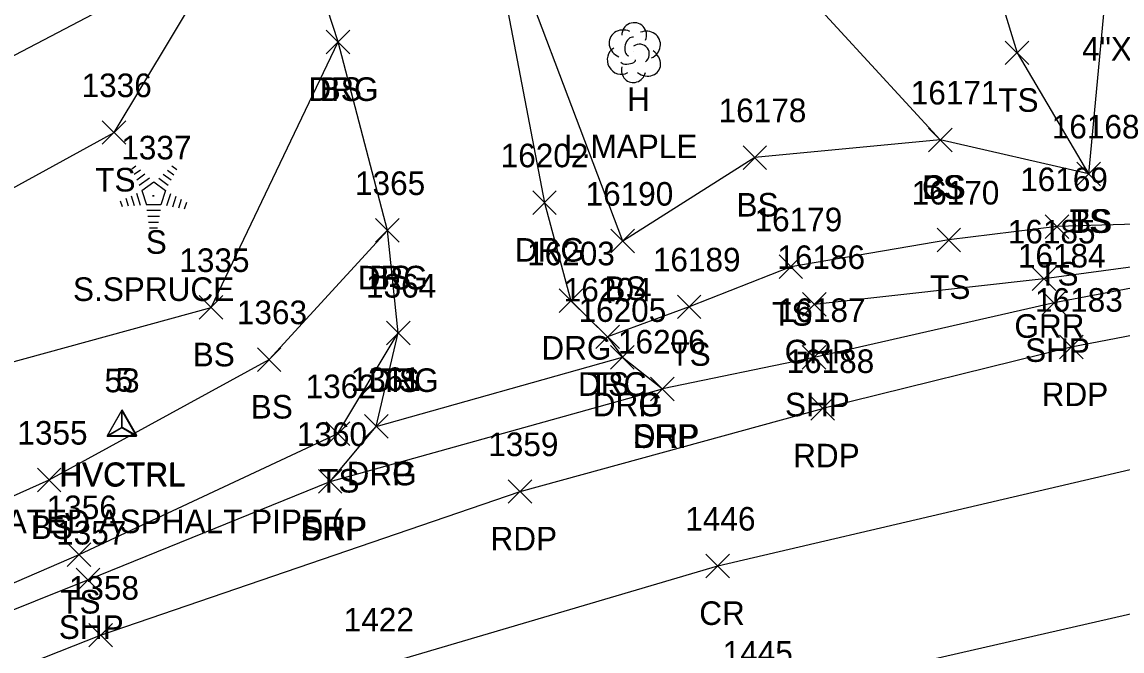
# Model space of a CAD drawing. Extents: x 1606530 to 1613020, y 784959 to 789666.
# Drawn here: x 1609059.8 to 1609153.1, y 788414.2 to 788467.6 of the extents above; entities that cross this region are included whole.
import ezdxf

# ---------------------------------------------------------------- set-up
doc = ezdxf.new("R2010")
doc.units = 0
for name, color, linetype in [('C_A', 7, 'Continuous'), ('C_C', 7, 'Continuous'), ('C_I', 7, 'Continuous'), ('CPSM', 7, 'Continuous'), ('L_A', 7, 'Continuous'), ('L_C', 7, 'Continuous'), ('L_I', 7, 'Continuous'), ('L_TIC', 7, 'Continuous'), ('LAPB', 7, 'Continuous'), ('LELB', 7, 'Continuous'), ('LTC', 7, 'Continuous'), ('LTD', 7, 'Continuous'), ('M_C', 7, 'Continuous'), ('P_A', 7, 'Continuous'), ('P_I', 7, 'Continuous'), ('P_TIC', 7, 'Continuous'), ('PET', 7, 'Continuous'), ('PRC', 7, 'Continuous'), ('PSP', 7, 'Continuous'), ('R_A', 7, 'Continuous'), ('R_I', 7, 'Continuous'), ('R_TIC', 7, 'Continuous'), ('RDG', 7, 'Continuous'), ('RDP', 7, 'Continuous'), ('RGR', 7, 'Continuous')]:
    doc.layers.add(name, color=color, linetype=linetype)

msp = doc.modelspace()

# ---------------------------------------------------------------- linework, layer by layer
at = {"layer": 'CPSM'}
for p, q in [((1609067.029, 788432.449), (1609068.279, 788434.614)), ((1609067.07, 788432.503), (1609068.32, 788434.668)), ((1609069.529, 788432.449), (1609068.279, 788434.614)), ((1609068.279, 788433.17), (1609068.279, 788434.614)), ((1609069.57, 788432.503), (1609068.32, 788434.668)), ((1609068.32, 788433.224), (1609068.32, 788434.668)), ((1609067.029, 788432.449), (1609068.279, 788433.17)), ((1609067.07, 788432.503), (1609068.32, 788433.224)), ((1609068.279, 788433.17), (1609068.279, 788433.17)), ((1609068.279, 788433.17), (1609069.529, 788432.449)), ((1609068.32, 788433.224), (1609068.32, 788433.224)), ((1609068.32, 788433.224), (1609069.57, 788432.503)), ((1609067.029, 788432.449), (1609069.529, 788432.449)), ((1609067.07, 788432.503), (1609069.57, 788432.503))]:
    msp.add_line(p, q, dxfattribs=at)
at = {"layer": 'L_TIC'}
for points in [[(1609085.615, 788464.867), (1609087.615, 788466.867)], [(1609087.615, 788464.867), (1609085.615, 788466.867)], [(1609143.18, 788463.944), (1609145.18, 788465.944)], [(1609145.18, 788463.944), (1609143.18, 788465.944)], [(1609066.622, 788457.189), (1609068.622, 788459.189)], [(1609068.622, 788457.189), (1609066.622, 788459.189)], [(1609136.675, 788456.565), (1609138.675, 788458.565)], [(1609138.675, 788456.565), (1609136.675, 788458.565)], [(1609136.675, 788456.565), (1609138.675, 788458.565)], [(1609138.675, 788456.565), (1609136.675, 788458.565)], [(1609120.952, 788455.066), (1609122.952, 788457.066)], [(1609122.952, 788455.066), (1609120.952, 788457.066)], [(1609149.242, 788453.683), (1609151.242, 788455.683)], [(1609151.242, 788453.683), (1609149.242, 788455.683)], [(1609149.242, 788453.683), (1609151.242, 788455.683)], [(1609151.242, 788453.683), (1609149.242, 788455.683)], [(1609089.795, 788448.892), (1609091.795, 788450.892)], [(1609091.795, 788448.892), (1609089.795, 788450.892)], [(1609146.57, 788449.219), (1609148.57, 788451.219)], [(1609148.57, 788449.219), (1609146.57, 788451.219)], [(1609109.755, 788447.99), (1609111.755, 788449.99)], [(1609111.755, 788447.99), (1609109.755, 788449.99)], [(1609137.4, 788448.085), (1609139.4, 788450.085)], [(1609139.4, 788448.085), (1609137.4, 788450.085)], [(1609124.003, 788445.816), (1609126.003, 788447.816)], [(1609126.003, 788445.816), (1609124.003, 788447.816)], [(1609074.854, 788442.367), (1609076.854, 788444.367)], [(1609076.854, 788442.367), (1609074.854, 788444.367)], [(1609115.381, 788442.414), (1609117.381, 788444.414)], [(1609117.381, 788442.414), (1609115.381, 788444.414)], [(1609090.726, 788440.196), (1609092.726, 788442.196)], [(1609092.726, 788440.196), (1609090.726, 788442.196)], [(1609108.467, 788439.866), (1609110.467, 788441.866)], [(1609110.467, 788439.866), (1609108.467, 788441.866)], [(1609079.774, 788437.941), (1609081.774, 788439.941)], [(1609081.774, 788437.941), (1609079.774, 788439.941)], [(1609085.607, 788431.669), (1609087.607, 788433.669)], [(1609087.607, 788431.669), (1609085.607, 788433.669)], [(1609061.123, 788427.733), (1609063.123, 788429.733)], [(1609063.123, 788427.733), (1609061.123, 788429.733)], [(1609063.659, 788421.412), (1609065.659, 788423.412)], [(1609065.659, 788421.412), (1609063.659, 788423.412)]]:
    msp.add_lwpolyline(points, dxfattribs=at)
at = {"layer": 'LAPB'}
msp.add_lwpolyline([(1609039.186, 788456.559), (1609048.843, 788460.874), (1609049.597, 788459.75), (1609077.276, 788474.239), (1609077.034, 788475.297)], dxfattribs=at)
at = {"layer": 'LELB'}
for points in [[(1609129.406, 788518.122), (1609137.084, 788488.072), (1609144.18, 788464.944), (1609150.242, 788454.683)], [(1609137.675, 788457.565), (1609120.211, 788476.589), (1609108.336, 788494.696), (1609102.619, 788504.963)], [(1609154.118, 788496.013), (1609150.242, 788454.683), (1609137.675, 788457.565), (1609121.952, 788456.066), (1609110.755, 788448.99), (1609098.581, 788481.172)], [(1609023.982, 788453.352), (1609032.544, 788443.85), (1609054.318, 788450.9), (1609067.622, 788458.189), (1609077.276, 788474.239)], [(1609032.544, 788443.85), (1609044.285, 788434.696), (1609075.854, 788443.367), (1609086.615, 788465.867)], [(1609168.452, 788450.858), (1609147.57, 788450.219), (1609138.4, 788449.085), (1609125.003, 788446.816), (1609116.381, 788443.414), (1609109.467, 788440.866)], [(1608946.183, 788421.743), (1608965.259, 788393.752), (1608969.902, 788390.672), (1608981.426, 788393.597), (1608995.3, 788400.266), (1609013.646, 788407.887), (1609037.315, 788417.629), (1609062.123, 788428.733), (1609080.774, 788438.941), (1609090.795, 788449.892)], [(1608977.618, 788385.058), (1608987.682, 788388.705), (1609017.024, 788403.26), (1609039.259, 788411.433), (1609064.659, 788422.412), (1609086.607, 788432.669), (1609091.726, 788441.196)]]:
    msp.add_lwpolyline(points, dxfattribs=at)
at = {"layer": 'LTC'}
for p, q in [((1609069.124, 788455.118), (1609069.478, 788455.376)), ((1609069.333, 788454.653), (1609069.863, 788455.037)), ((1609072.151, 788455.011), (1609072.7, 788454.611)), ((1609072.522, 788455.359), (1609072.941, 788455.054)), ((1609069.543, 788454.187), (1609070.247, 788454.698)), ((1609069.753, 788453.721), (1609070.631, 788454.359)), ((1609071.409, 788454.314), (1609072.218, 788453.725)), ((1609071.78, 788454.662), (1609072.459, 788454.168)), ((1609069.977, 788453.266), (1609070.989, 788454.001)), ((1609069.977, 788453.266), (1609070.364, 788452.073)), ((1609070.989, 788454.001), (1609071.986, 788453.276)), ((1609071.986, 788453.276), (1609071.595, 788452.073)), ((1609068.156, 788452.398), (1609068.308, 788451.93)), ((1609068.612, 788452.614), (1609068.823, 788451.963)), ((1609069.067, 788452.831), (1609069.338, 788451.996)), ((1609069.523, 788453.047), (1609069.853, 788452.028)), ((1609072.423, 788453.005), (1609072.085, 788451.966)), ((1609072.868, 788452.755), (1609072.58, 788451.87)), ((1609073.313, 788452.505), (1609073.075, 788451.775)), ((1609073.757, 788452.254), (1609073.57, 788451.68)), ((1609071.595, 788452.073), (1609070.364, 788452.073)), ((1609071.556, 788451.573), (1609070.412, 788451.573)), ((1609071.473, 788451.073), (1609070.484, 788451.073)), ((1609071.389, 788450.573), (1609070.557, 788450.573)), ((1609071.305, 788450.073), (1609070.63, 788450.073))]:
    msp.add_line(p, q, dxfattribs=at)
at = {"layer": 'LTD'}
msp.add_line((1609111.677, 788465.016), (1609111.677, 788465.016), dxfattribs=at)
msp.add_line((1609111.677, 788465.016), (1609111.677, 788465.016), dxfattribs=at)
msp.add_arc((1609111.723, 788466.45), 1.047, 335.52715, 180.95627, dxfattribs=at)
for centre, major_axis, ratio, start_param, end_param in [((1609110.885, 788465.683), (1.21, -0.512), 0.895232, 1.570796, 4.712389), ((1609111.468, 788465.475), (-0.208, -0.792), 0.645439, 3.141593, 6.283185), ((1609112.718, 788465.6), (-1.141, -0.483), 0.949671, 1.570796, 4.712389), ((1609110.594, 788464.308), (0.584, -1.042), 0.959034, 3.141593, 6.283185), ((1609112.177, 788464.85), (-0.5, 0.667), 0.989748, 3.141593, 6.283185), ((1609111.219, 788464.266), (-0.625, -0.083), 0.423636, 0, 3.141593), ((1609112.677, 788464.183), (-1.09, 0.792), 0.841452, 1.570796, 4.712389), ((1609111.677, 788463.516), (0.265, 1.061), 0.942809, 1.570796, 4.712389)]:
    msp.add_ellipse(centre, major_axis=major_axis, ratio=ratio, start_param=start_param, end_param=end_param, dxfattribs=at)
at = {"layer": 'P_TIC'}
for points in [[(1609146.32, 788442.745), (1609148.32, 788444.745)], [(1609148.32, 788442.745), (1609146.32, 788444.745)], [(1609147.778, 788438.997), (1609149.778, 788440.997)], [(1609149.778, 788438.997), (1609147.778, 788440.997)], [(1609125.968, 788438.128), (1609127.968, 788440.128)], [(1609127.968, 788438.128), (1609125.968, 788440.128)], [(1609113.118, 788435.455), (1609115.118, 788437.455)], [(1609115.118, 788435.455), (1609113.118, 788437.455)], [(1609113.118, 788435.455), (1609115.118, 788437.455)], [(1609115.118, 788435.455), (1609113.118, 788437.455)], [(1609126.707, 788433.803), (1609128.707, 788435.803)], [(1609128.707, 788433.803), (1609126.707, 788435.803)], [(1609126.707, 788433.803), (1609128.707, 788435.803)], [(1609128.707, 788433.803), (1609126.707, 788435.803)], [(1609084.948, 788427.615), (1609086.948, 788429.615)], [(1609086.948, 788427.615), (1609084.948, 788429.615)], [(1609101.049, 788426.759), (1609103.049, 788428.759)], [(1609103.049, 788426.759), (1609101.049, 788428.759)], [(1609117.805, 788420.444), (1609119.805, 788422.444)], [(1609119.805, 788420.444), (1609117.805, 788422.444)], [(1609064.41, 788419.262), (1609066.41, 788421.262)], [(1609066.41, 788419.262), (1609064.41, 788421.262)], [(1609065.482, 788414.581), (1609067.482, 788416.581)], [(1609067.482, 788414.581), (1609065.482, 788416.581)]]:
    msp.add_lwpolyline(points, dxfattribs=at)
at = {"layer": 'PET'}
for points in [[(1609713.165, 788438.627), (1609680.929, 788440.448), (1609651.997, 788442.015), (1609625.849, 788443.733), (1609580.961, 788446.419), (1609565.084, 788447.467), (1609525.711, 788449.455), (1609486.159, 788451.542), (1609451.915, 788453.585), (1609423.874, 788454.943), (1609378.56, 788456.924), (1609332.013, 788457.666), (1609286.402, 788456.921), (1609233.035, 788453.523), (1609189.077, 788447.384), (1609175.759, 788445.193), (1609148.778, 788439.997), (1609127.707, 788434.803)], [(1608827.199, 788266.245), (1608867.859, 788290.541), (1608906.681, 788312.856), (1608942.677, 788332.755), (1608980.541, 788352.164), (1609023.571, 788373.225), (1609061.437, 788389.904), (1609090.798, 788401.175), (1609121.915, 788410.089), (1609165.169, 788419.998), (1609195.853, 788425.54), (1609240.139, 788431.13), (1609287.877, 788434.372), (1609331.481, 788435.115), (1609378.889, 788434.051), (1609425.427, 788432.251), (1609443.83, 788431.331), (1609477.321, 788429.782), (1609518.441, 788427.602), (1609569.185, 788424.684), (1609602.993, 788422.58), (1609641.45, 788420.372), (1609681.697, 788417.919), (1609727.381, 788415.531)], [(1608858.102, 788310.732), (1608896.559, 788332.458), (1608932.583, 788352.682), (1608960.396, 788367.207), (1608987.919, 788381.261), (1609019.358, 788396.212), (1609040.554, 788405.359), (1609066.482, 788415.581), (1609102.049, 788427.759), (1609127.707, 788434.803)]]:
    msp.add_lwpolyline(points, dxfattribs=at)
at = {"layer": 'PRC'}
msp.add_lwpolyline([(1608863.252, 788300.903), (1608901.811, 788322.596), (1608937.609, 788342.722), (1608976.118, 788362.757), (1609017.577, 788382.951), (1609062.579, 788402.235), (1609089.789, 788412.891), (1609118.805, 788421.444), (1609162.845, 788431.752), (1609194.146, 788437.356), (1609237.64, 788442.85), (1609286.897, 788446.16), (1609332.711, 788446.436), (1609379.393, 788445.342), (1609425.621, 788443.432), (1609445.831, 788442.47), (1609477.779, 788440.947), (1609519.757, 788438.847), (1609569.723, 788435.898), (1609601.73, 788434.311), (1609642.39, 788431.817), (1609682.025, 788429.153), (1609726.546, 788426.785)], dxfattribs=at)
at = {"layer": 'PSP'}
for points in [[(1609713.922, 788443.117), (1609681.225, 788444.652), (1609657.996, 788445.994), (1609646.319, 788446.917), (1609626.337, 788447.989), (1609592.684, 788450.096), (1609566.898, 788451.268), (1609526.223, 788453.589), (1609486.022, 788455.2), (1609451.52, 788457.024), (1609423.816, 788458.463), (1609378.085, 788460.467), (1609331.883, 788461.682), (1609285.229, 788461.605), (1609232.595, 788457.915), (1609188.508, 788451.364), (1609172.5, 788448.52), (1609147.32, 788443.745), (1609126.968, 788439.128), (1609114.118, 788436.455)], [(1608855.389, 788314.113), (1608894.808, 788336.591), (1608931.247, 788356.378), (1608958.599, 788370.933), (1608985.981, 788385.272), (1609018.034, 788400.244), (1609039.035, 788409.707), (1609065.41, 788420.262), (1609085.948, 788428.615), (1609114.118, 788436.455)]]:
    msp.add_lwpolyline(points, dxfattribs=at)
at = {"layer": 'R_TIC'}
for points in [[(1609085.615, 788464.867), (1609087.615, 788466.867)], [(1609087.615, 788464.867), (1609085.615, 788466.867)], [(1609103.119, 788451.242), (1609105.119, 788453.242)], [(1609105.119, 788451.242), (1609103.119, 788453.242)], [(1609089.795, 788448.892), (1609091.795, 788450.892)], [(1609091.795, 788448.892), (1609089.795, 788450.892)], [(1609145.466, 788444.786), (1609147.466, 788446.786)], [(1609147.466, 788444.786), (1609145.466, 788446.786)], [(1609105.361, 788442.934), (1609107.361, 788444.934)], [(1609107.361, 788442.934), (1609105.361, 788444.934)], [(1609125.985, 788442.62), (1609127.985, 788444.62)], [(1609127.985, 788442.62), (1609125.985, 788444.62)], [(1609090.726, 788440.196), (1609092.726, 788442.196)], [(1609092.726, 788440.196), (1609090.726, 788442.196)], [(1609108.467, 788439.866), (1609110.467, 788441.866)], [(1609110.467, 788439.866), (1609108.467, 788441.866)], [(1609109.721, 788438.134), (1609111.721, 788440.134)], [(1609111.721, 788438.134), (1609109.721, 788440.134)], [(1609109.721, 788438.134), (1609111.721, 788440.134)], [(1609111.721, 788438.134), (1609109.721, 788440.134)], [(1609113.118, 788435.455), (1609115.118, 788437.455)], [(1609115.118, 788435.455), (1609113.118, 788437.455)], [(1609088.852, 788432.277), (1609090.852, 788434.277)], [(1609090.852, 788432.277), (1609088.852, 788434.277)], [(1609088.852, 788432.277), (1609090.852, 788434.277)], [(1609090.852, 788432.277), (1609088.852, 788434.277)], [(1609084.948, 788427.615), (1609086.948, 788429.615)], [(1609086.948, 788427.615), (1609084.948, 788429.615)]]:
    msp.add_lwpolyline(points, dxfattribs=at)
at = {"layer": 'RDG'}
for points in [[(1609089.488, 788509.207), (1609098.581, 788481.172), (1609104.119, 788452.242), (1609106.361, 788443.934), (1609109.467, 788440.866), (1609110.721, 788439.134)], [(1609089.852, 788433.277), (1609091.726, 788441.196), (1609090.795, 788449.892), (1609086.615, 788465.867), (1609082.535, 788478.447), (1609077.494, 788487.997), (1609069.815, 788503.317)]]:
    msp.add_lwpolyline(points, dxfattribs=at)
at = {"layer": 'RDP'}
msp.add_lwpolyline([(1609085.948, 788428.615), (1609089.852, 788433.277), (1609110.721, 788439.134), (1609114.118, 788436.455)], dxfattribs=at)
at = {"layer": 'RGR'}
msp.add_lwpolyline([(1609451.624, 788460.776), (1609423.64, 788459.824), (1609378.061, 788461.13), (1609332.058, 788462.447), (1609285.08, 788462.326), (1609232.465, 788458.698), (1609188.438, 788451.909), (1609171.832, 788449.191), (1609146.466, 788445.786), (1609126.985, 788443.62)], dxfattribs=at)

# ---------------------------------------------------------------- texts
at = {"layer": 'C_A'}
for p in [(1609062.972, 788428.17), (1609063.013, 788428.224)]:
    msp.add_text('HVCTRL', height=2, dxfattribs=at).set_placement(p)
at = {"layer": 'C_C'}
msp.add_text('4" PERFERATED ASPHALT PIPE (', height=2, dxfattribs=at).set_placement((1609044.415, 788424.224))
at = {"layer": 'C_I'}
for s, p in [('53', (1609066.814, 788436.17)), ('5', (1609067.753, 788436.224))]:
    msp.add_text(s, height=2, dxfattribs=at).set_placement(p)
at = {"layer": 'L_A'}
for s, p in [('BS', (1609085.056, 788460.867)), ('H', (1609111.11, 788460.016)), ('TS', (1609142.589, 788459.944)), ('TS', (1609066.031, 788453.189)), ('CS', (1609136.116, 788452.565)), ('BS', (1609136.116, 788452.565)), ('BS', (1609120.393, 788451.066)), ('TS', (1609148.651, 788449.683)), ('BS', (1609148.683, 788449.683)), ('S', (1609070.314, 788447.91)), ('BS', (1609089.236, 788444.892)), ('TS', (1609145.979, 788445.219)), ('BS', (1609109.196, 788443.99)), ('TS', (1609136.81, 788444.085)), ('TS', (1609123.412, 788441.816)), ('BS', (1609074.295, 788438.367)), ('TS', (1609114.791, 788438.414)), ('TS', (1609090.135, 788436.196)), ('TS', (1609107.877, 788435.866)), ('BS', (1609079.215, 788433.941)), ('TS', (1609085.016, 788427.669)), ('BS', (1609060.564, 788423.733)), ('TS', (1609063.068, 788417.412))]:
    msp.add_text(s, height=2, dxfattribs=at).set_placement(p)
at = {"layer": 'L_C'}
for s, p in [('L.MAPLE', (1609105.787, 788456.016)), ('S.SPRUCE', (1609064.141, 788443.91))]:
    msp.add_text(s, height=2, dxfattribs=at).set_placement(p)
at = {"layer": 'L_I'}
for s, p in [('1336', (1609064.874, 788461.189)), ('16171', (1609135.171, 788460.565)), ('16171', (1609135.171, 788460.565)), ('16178', (1609118.881, 788459.066)), ('16168', (1609147.124, 788457.683)), ('16168', (1609147.124, 788457.683)), ('1337', (1609068.236, 788455.91)), ('16169', (1609144.444, 788453.219)), ('1365', (1609088.055, 788452.892)), ('16170', (1609135.243, 788452.085)), ('16190', (1609107.598, 788451.99)), ('16179', (1609121.925, 788449.816)), ('16189', (1609113.303, 788446.414)), ('1335', (1609073.161, 788446.367)), ('1364', (1609088.986, 788444.196)), ('16204', (1609105.751, 788443.866)), ('1363', (1609078.034, 788441.941)), ('1362', (1609083.867, 788435.669)), ('1355', (1609059.43, 788431.733)), ('1356', (1609061.911, 788425.412))]:
    msp.add_text(s, height=2, dxfattribs=at).set_placement(p)
at = {"layer": 'LTC'}
msp.add_text('.', height=1.037, rotation=270, dxfattribs=at).set_placement((1609070.871, 788453.014))
at = {"layer": 'M_C'}
msp.add_text('4"X4" CONC 4"AGS', height=2, dxfattribs=at).set_placement((1609149.697, 788464.287))
at = {"layer": 'P_A'}
for s, p in [('SHP', (1609144.856, 788438.745)), ('RDP', (1609146.267, 788434.997)), ('SHP', (1609124.503, 788434.128)), ('SHP', (1609111.654, 788431.455)), ('SHP', (1609111.654, 788431.455)), ('RDP', (1609125.195, 788429.803)), ('RDP', (1609125.195, 788429.803)), ('SHP', (1609083.484, 788423.615)), ('RDP', (1609099.537, 788422.759)), ('CR', (1609117.238, 788416.444)), ('SHP', (1609062.946, 788415.262))]:
    msp.add_text(s, height=2, dxfattribs=at).set_placement(p)
at = {"layer": 'P_I'}
for s, p in [('16184', (1609144.25, 788446.745)), ('16183', (1609145.708, 788442.997)), ('16187', (1609123.897, 788442.128)), ('16206', (1609110.347, 788439.455)), ('16206', (1609110.347, 788439.455)), ('16188', (1609124.637, 788437.803)), ('16188', (1609124.637, 788437.803)), ('1360', (1609083.122, 788431.615)), ('1359', (1609099.349, 788430.759)), ('1446', (1609116.057, 788424.444)), ('1357', (1609062.717, 788423.262)), ('1358', (1609063.789, 788418.581)), ('1422', (1609087.097, 788415.891)), ('1445', (1609119.222, 788413.089))]:
    msp.add_text(s, height=2, dxfattribs=at).set_placement(p)
at = {"layer": 'R_A'}
for s, p in [('DRG', (1609084.104, 788460.867)), ('DRG', (1609101.607, 788447.242)), ('DRG', (1609088.283, 788444.892)), ('GRR', (1609143.954, 788440.786)), ('DRG', (1609103.849, 788438.934)), ('GRR', (1609124.473, 788438.62)), ('DRG', (1609089.214, 788436.196)), ('DRG', (1609106.955, 788435.866)), ('DRG', (1609108.209, 788434.134)), ('DRP', (1609108.209, 788434.134)), ('DRP', (1609111.607, 788431.455)), ('DRG', (1609087.34, 788428.277)), ('DRP', (1609087.34, 788428.277)), ('DRP', (1609083.436, 788423.615))]:
    msp.add_text(s, height=2, dxfattribs=at).set_placement(p)
at = {"layer": 'R_I'}
for s, p in [('16202', (1609100.402, 788455.242)), ('1365', (1609088.055, 788452.892)), ('16185', (1609143.395, 788448.786)), ('16203', (1609102.644, 788446.934)), ('16186', (1609123.859, 788446.62)), ('1364', (1609088.986, 788444.196)), ('16204', (1609105.751, 788443.866)), ('16205', (1609107.005, 788442.134)), ('16205', (1609107.005, 788442.134)), ('16206', (1609110.347, 788439.455)), ('1361', (1609087.679, 788436.277)), ('1361', (1609087.679, 788436.277)), ('1360', (1609083.122, 788431.615))]:
    msp.add_text(s, height=2, dxfattribs=at).set_placement(p)

doc.saveas('drawing.dxf')
